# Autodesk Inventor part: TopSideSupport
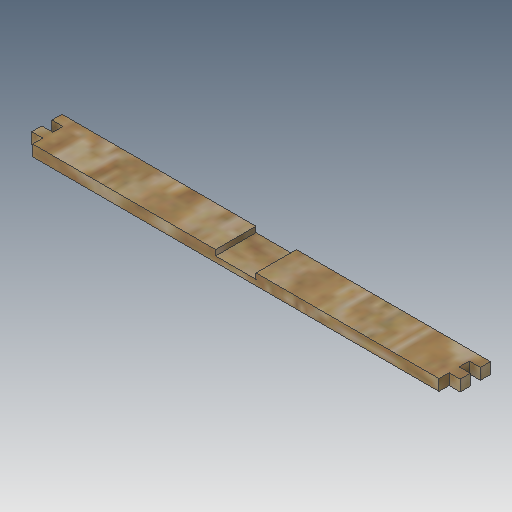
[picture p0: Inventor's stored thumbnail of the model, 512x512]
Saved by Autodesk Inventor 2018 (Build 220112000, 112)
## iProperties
Created: 2018-05
Part Number: TopSideSupport
Material: Generic
Document SubType Name: Modeling
Designer: arivu
Density: 1 g/cm^3
Appearance: Default
Author: arivu
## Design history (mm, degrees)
derived "WaterTank.ipt"
feature "Solid13::WaterTank.ipt" dims "d0" = 10
tag "TaggingFeature1"
body "Solid1"
